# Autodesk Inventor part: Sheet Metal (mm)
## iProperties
Shininess: 64.0
Length Units: 11269
Angle Units: 11279
Time Units: 11290
Mass Units: 11283
Length Display Precision: 3
Angle Display Precision: 2
Compacted: True
Part Number: Sheet Metal (mm)
Document SubType Name: Sheet Metal
Created: 2002-07
Density: 1 g/cm^3
Density: 0.0
Volumn: 0.0
Area: 0.0
PropertySet Name: Model Information
Control State: 0
Master: False
Checked Out: False
